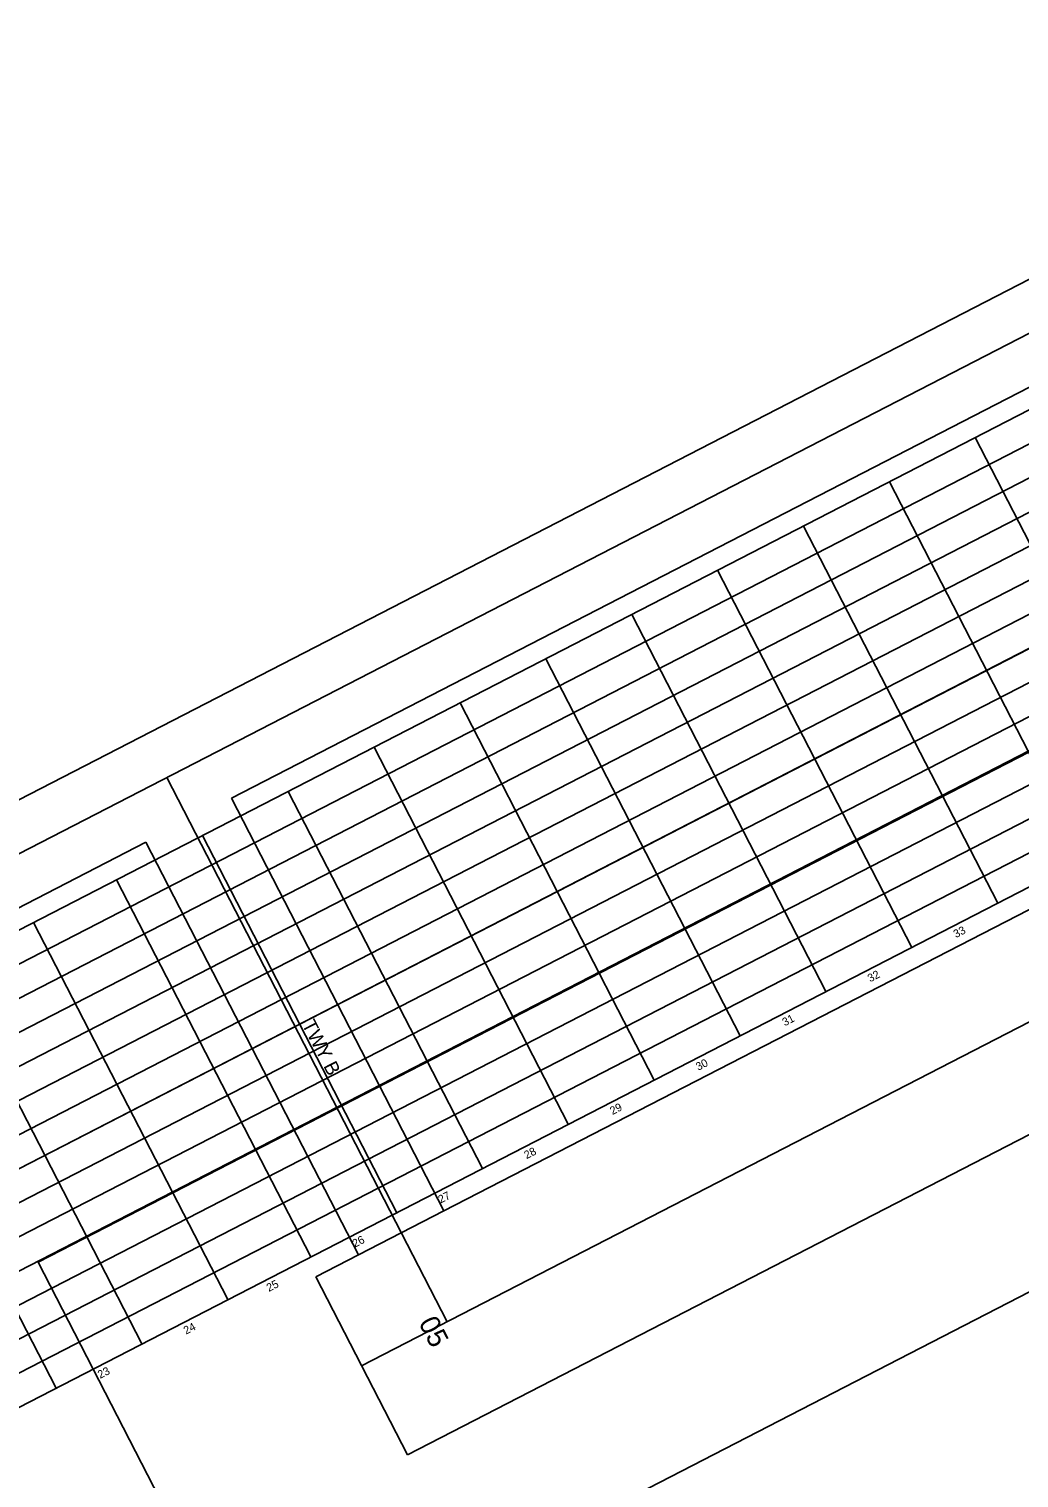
# Model space of a CAD drawing. Extents: x -886320 to -884760, y -1024172 to -1023483.
# Drawn here: x -885773.4 to -885649.7, y -1024061.4 to -1023880.4 of the extents above; entities that cross this region are included whole.
import ezdxf

# ---------------------------------------------------------------- set-up
doc = ezdxf.new("R2010")
doc.units = 0
for name, color, linetype in [('AGA__Netisknout', 7, 'Continuous'), ('Stavajici_betonova_draha', 7, 'Continuous'), ('Stavajici_betonova_draha_osa', 7, 'Continuous'), ('Stavajici_betonova_draha_Popis desky', 7, 'Continuous'), ('Stavajici_betonova_draha_Spára', 7, 'Continuous'), ('Stavajici_drahovy_system', 7, 'Continuous'), ('Stavajici_drahovy_system_osy', 7, 'Continuous'), ('Stavajici_drahovy_system_popis', 7, 'Continuous'), ('Stavajici_drahovy_system_RWY_strip', 7, 'Continuous'), ('Stavajici_drahovy_system_TWY', 7, 'Continuous'), ('Stavajici_drahovy_system_TWY_osy', 7, 'Continuous'), ('Stavajici_drahovy_system_TWY_popis', 7, 'Continuous')]:
    doc.layers.add(name, color=color, linetype=linetype)

msp = doc.modelspace()

# ---------------------------------------------------------------- linework, layer by layer
at = {"layer": 'AGA__Netisknout'}
msp.add_line((-886017.78, -1024147.99), (-884773.13, -1023507.02), dxfattribs=at)
at = {"layer": 'Stavajici_betonova_draha'}
for p, q in [((-886029.69, -1024124.32), (-884785.04, -1023483.35)), ((-886029.69, -1024124.32), (-884785.04, -1023483.35)), ((-886005.42, -1024171.44), (-884760.77, -1023530.47)), ((-886005.42, -1024171.44), (-884760.77, -1023530.47))]:
    msp.add_line(p, q, dxfattribs=at)
at = {"layer": 'Stavajici_betonova_draha_osa'}
msp.add_line((-886017.55, -1024147.88), (-884772.9, -1023506.91), dxfattribs=at)
at = {"layer": 'Stavajici_betonova_draha_Spára'}
for p, q in [((-886029.91, -1024124.43), (-884785.26, -1023483.46)), ((-886028.18, -1024127.8), (-884783.53, -1023486.82)), ((-886026.44, -1024131.16), (-884781.79, -1023490.19)), ((-886024.71, -1024134.53), (-884780.06, -1023493.56)), ((-886022.98, -1024137.89), (-884778.33, -1023496.92)), ((-886021.24, -1024141.26), (-884776.59, -1023500.29)), ((-886019.51, -1024144.63), (-884774.86, -1023503.65)), ((-886016.04, -1024151.36), (-884771.39, -1023510.39)), ((-886014.31, -1024154.72), (-884769.66, -1023513.75)), ((-886012.58, -1024158.09), (-884767.93, -1023517.12)), ((-886010.84, -1024161.46), (-884766.19, -1023520.48)), ((-886009.11, -1024164.82), (-884764.46, -1023523.85)), ((-886007.38, -1024168.19), (-884762.73, -1023527.21)), ((-886005.64, -1024171.55), (-884760.99, -1023530.58)), ((-885655.16, -1023931.44), (-885630.9, -1023978.57)), ((-885665.89, -1023936.97), (-885641.63, -1023984.09)), ((-885676.62, -1023942.49), (-885652.36, -1023989.62)), ((-885687.35, -1023948.02), (-885663.09, -1023995.14)), ((-885698.08, -1023953.55), (-885673.82, -1024000.67)), ((-885708.81, -1023959.07), (-885684.55, -1024006.19)), ((-885719.54, -1023964.6), (-885695.28, -1024011.72)), ((-885730.27, -1023970.12), (-885706.01, -1024017.25)), ((-885741, -1023975.65), (-885716.73, -1024022.77)), ((-885751.73, -1023981.17), (-885727.46, -1024028.3)), ((-885762.46, -1023986.7), (-885738.19, -1024033.82)), ((-885772.83, -1023992.04), (-885748.56, -1024039.16)), ((-885783.56, -1023997.57), (-885759.29, -1024044.69)), ((-885794.29, -1024003.09), (-885770.02, -1024050.21))]:
    msp.add_line(p, q, dxfattribs=at)
at = {"layer": 'Stavajici_drahovy_system'}
for p, q in [((-885721.56, -1024028.07), (-884864.53, -1023586.71)), ((-885726.12, -1024058.54), (-884837.08, -1023600.7)), ((-885744.78, -1024087.83), (-884802.4, -1023602.52)), ((-885737.57, -1024036.31), (-885721.56, -1024028.07)), ((-885737.57, -1024036.31), (-885726.12, -1024058.54))]:
    msp.add_line(p, q, dxfattribs=at)
at = {"layer": 'Stavajici_drahovy_system_osy'}
msp.add_line((-885731.84, -1024047.42), (-884842.81, -1023589.59), dxfattribs=at)
at = {"layer": 'Stavajici_drahovy_system_RWY_strip'}
for p, q in [((-885772.25, -1024034.49), (-884829.87, -1023549.18)), ((-884802.4, -1023602.52), (-885744.78, -1024087.83)), ((-885744.78, -1024087.83), (-885772.25, -1024034.49))]:
    msp.add_line(p, q, dxfattribs=at)
at = {"layer": 'Stavajici_drahovy_system_TWY'}
for p, q in [((-885887.27, -1024034.67), (-884885.91, -1023518.99)), ((-885748.12, -1023976.51), (-884891.09, -1023535.15)), ((-885721.56, -1024028.07), (-885748.12, -1023976.51)), ((-885886.13, -1024047.58), (-885758.79, -1023982)), ((-885732.23, -1024033.56), (-885758.79, -1023982))]:
    msp.add_line(p, q, dxfattribs=at)
at = {"layer": 'Stavajici_drahovy_system_TWY_osy'}
for p, q in [((-885886.7, -1024041.13), (-884883.17, -1023524.32)), ((-885721.17, -1024041.93), (-885756.2, -1023973.92))]:
    msp.add_line(p, q, dxfattribs=at)

# ---------------------------------------------------------------- texts
at = {"layer": 'Stavajici_betonova_draha_Popis desky'}
for s, p in [('33', (-885657.58, -1023993.99)), ('32', (-885668.3, -1023999.52)), ('31', (-885678.97, -1024005.01)), ('30', (-885689.77, -1024010.57)), ('29', (-885700.5, -1024016.1)), ('28', (-885711.23, -1024021.62)), ('27', (-885721.96, -1024027.15)), ('26', (-885732.68, -1024032.67)), ('25', (-885743.42, -1024038.2)), ('24', (-885753.78, -1024043.54)), ('23', (-885764.51, -1024049.06))]:
    msp.add_text(s, height=1, rotation=27.2477, dxfattribs=at).set_placement(p)
at = {"layer": 'Stavajici_drahovy_system_popis'}
msp.add_text('05', height=2.5, rotation=297.2477, dxfattribs=at).set_placement((-885724.77, -1024042.05))
at = {"layer": 'Stavajici_drahovy_system_TWY_popis'}
msp.add_text('TWY B', height=1.75, rotation=297.2477, dxfattribs=at).set_placement((-885739.34, -1024004.75))

doc.saveas('drawing.dxf')
